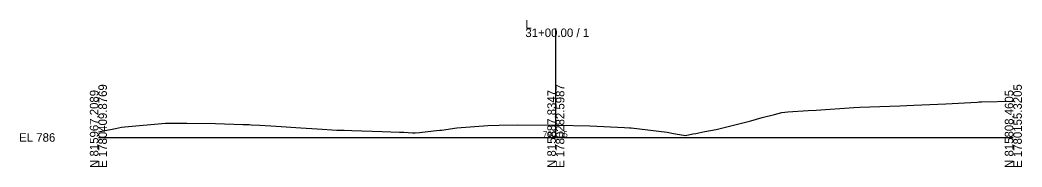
# Model space of a CAD drawing. Extents: x -26 to 7903, y -10 to 9573.
# Drawn here: x -25.7 to 302.8, y 1990.3 to 2038.6 of the extents above; entities that cross this region are included whole.
import ezdxf

# ---------------------------------------------------------------- set-up
doc = ezdxf.new("R2010")
doc.units = 0
for name, color, linetype in [('Exist Cross Section Cell', 7, 'Continuous'), ('Exist XS Center Line Elevation Label', 7, 'Continuous'), ('Exist XS Ground Line', 7, 'Continuous')]:
    doc.layers.add(name, color=color, linetype=linetype)

msp = doc.modelspace()

# ---------------------------------------------------------------- linework, layer by layer
at = {"layer": 'Exist Cross Section Cell'}
for p, q in [((150, 2000), (150, 2035.77)), ((0, 2000), (150, 2000)), ((150, 2000), (300, 2000))]:
    msp.add_line(p, q, dxfattribs=at)
at = {"layer": 'Exist XS Ground Line'}
for p, q in [((267.41, 2010.56), (277.87, 2011.05)), ((277.87, 2011.05), (288.18, 2011.64)), ((288.18, 2011.64), (288.79, 2011.65)), ((288.79, 2011.65), (289.58, 2011.67)), ((289.58, 2011.67), (300, 2011.92)), ((217.63, 2006.57), (221.67, 2007.51)), ((221.67, 2007.51), (224.14, 2008.15)), ((224.14, 2008.15), (226.08, 2008.37)), ((226.08, 2008.37), (232.69, 2008.84)), ((232.69, 2008.84), (235.34, 2008.97)), ((235.34, 2008.97), (247.71, 2009.85)), ((247.71, 2009.85), (249.66, 2009.99)), ((249.66, 2009.99), (262.79, 2010.36)), ((262.79, 2010.36), (267.41, 2010.56)), ((8.64, 2003.51), (22.02, 2004.68)), ((22.02, 2004.68), (22.98, 2004.68)), ((22.98, 2004.68), (26.17, 2004.7)), ((26.17, 2004.7), (29.01, 2004.66)), ((29.01, 2004.66), (38.43, 2004.55)), ((38.43, 2004.55), (47.35, 2004.29)), ((47.35, 2004.29), (49.43, 2004.23)), ((49.43, 2004.23), (50.07, 2004.2)), ((50.07, 2004.2), (52.89, 2004.05)), ((52.89, 2004.05), (58.29, 2003.68)), ((131.46, 2004.03), (137.57, 2004.16)), ((137.57, 2004.16), (148.56, 2004.07)), ((148.56, 2004.07), (149.03, 2004.07)), ((149.03, 2004.07), (150, 2004.05)), ((202.55, 2002.67), (210.03, 2004.45)), ((210.03, 2004.45), (213.02, 2005.24)), ((213.02, 2005.24), (213.9, 2005.47)), ((213.9, 2005.47), (217.63, 2006.57)), ((0, 2001.83), (1.66, 2002.16)), ((1.66, 2002.16), (5.63, 2002.96)), ((5.63, 2002.96), (7.55, 2003.41)), ((7.55, 2003.41), (8.64, 2003.51)), ((58.29, 2003.68), (66.38, 2003.15)), ((66.38, 2003.15), (71.77, 2002.81)), ((71.77, 2002.81), (78.22, 2002.43)), ((78.22, 2002.43), (80.61, 2002.36)), ((80.61, 2002.36), (83.1, 2002.29)), ((83.1, 2002.29), (93.09, 2002)), ((93.09, 2002), (95.85, 2001.89)), ((95.85, 2001.89), (98.74, 2001.78)), ((98.74, 2001.78), (100.1, 2001.71)), ((100.1, 2001.71), (103.02, 2001.53)), ((103.02, 2001.53), (103.89, 2001.52)), ((103.89, 2001.52), (105.34, 2001.67)), ((105.34, 2001.67), (109.83, 2002.13)), ((109.83, 2002.13), (110.88, 2002.25)), ((110.88, 2002.25), (112.01, 2002.35)), ((112.01, 2002.35), (112.49, 2002.43)), ((112.49, 2002.43), (117.54, 2003.19)), ((117.54, 2003.19), (127.68, 2003.89)), ((127.68, 2003.89), (131.46, 2004.03)), ((150, 2004.05), (150.34, 2004.04)), ((150.34, 2004.04), (161.16, 2003.83)), ((161.16, 2003.83), (172.51, 2003.31)), ((172.51, 2003.31), (174.2, 2003.21)), ((174.2, 2003.21), (174.69, 2003.15)), ((174.69, 2003.15), (186.45, 2001.69)), ((186.45, 2001.69), (188.54, 2001.32)), ((188.54, 2001.32), (192.5, 2000.69)), ((192.5, 2000.69), (194.97, 2001.14)), ((194.97, 2001.14), (195.86, 2001.35)), ((195.86, 2001.35), (198.83, 2001.93)), ((198.83, 2001.93), (202.55, 2002.67))]:
    msp.add_line(p, q, dxfattribs=at)

# ---------------------------------------------------------------- texts
at = {"layer": 'Exist Cross Section Cell'}
for s, p in [('L', (140, 2035.77)), ('31+00.00 / 1', (140, 2032.97)), ('EL 786', (-26, 1998.6))]:
    msp.add_text(s, height=2.8, dxfattribs=at).set_placement(p)
for s, p in [('E 1780409.8769', (2.8, 1990)), ('E 1780282.5987', (152.8, 1990)), ('E 1780155.3205', (302.8, 1990)), ('N 815967.2089', (0, 1990)), ('N 815887.8347', (150, 1990)), ('N 815808.4605', (300, 1990))]:
    msp.add_text(s, height=2.8, rotation=90, dxfattribs=at).set_placement(p)
at = {"layer": 'Exist XS Center Line Elevation Label'}
msp.add_text('790.05', height=2, dxfattribs=at).set_placement((145.74, 2000.05))

doc.saveas('drawing.dxf')
